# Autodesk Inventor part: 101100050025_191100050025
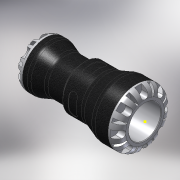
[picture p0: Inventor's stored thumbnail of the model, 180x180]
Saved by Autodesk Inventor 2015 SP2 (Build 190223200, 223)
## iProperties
Created: 2016-12
Part Number: 101100050025_191100050025
Material: PVC-Piping
Description: PLASSON REDUCING COUPLING 50X25 SERIES 1
Document SubType Name: Modeling
Designer: KIM
Mass: 369.856 g
Surface Area: 572.366 cm^2
Volume: 264.183 cm^3
Density: 1.4 g/cm^3
Appearance: Black Cast
Author: KIM
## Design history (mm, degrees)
derived "1011.ipt"
feature "Solid1::1011.ipt"
tag "TaggingFeature1"
body "Solid1"
other parameters: "d0" = 151, "d2" = 33.18, "d4" = 85, "d6" = 79, "d7" = 4.16667, "d8" = 47, "d9" = 25, "d10" = 31.25, "d11" = 21.42, "d12" = 51, "d13" = 2.08333, "d14" = 68, "d15" = 37.6, "d16" = 20 deg, "d17" = 20 deg, "d18" = 130 deg, "d26" = 0, "d28" = 360 deg, "d30" = 8 deg, "d31" = 1, "d32" = 8 deg, "d33" = 1, "d35" = 0, "d37" = 360 deg, "d39" = 6.3, "d42" = 6.3, "d43" = 0, "d45" = 360 deg, "d47" = 0.5, "d48" = 8 deg, "d49" = 8 deg, "d50" = 0.5, "d52" = 0, "d54" = 360 deg, "d56" = 9.4, "d57" = 17, "d58" = 0.5, "d60" = 10.2, "d61" = 12.5, "d62" = 16.2, "d63" = 0, "d66" = 0, "d68" = 360 deg, "d75" = 8.49071, "d77" = 66.3, "d78" = 0.85, "d1" = 25, "E_" = 85, "H_" = 151, "l_" = 79, "E1" = 47, "l1" = 51, "Plasson" = 1, "d20" = 7.875, "d21" = 12.5, "d23" = 85, "d40" = 47, "d41" = 31.25, "d59" = 16.98142
